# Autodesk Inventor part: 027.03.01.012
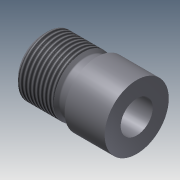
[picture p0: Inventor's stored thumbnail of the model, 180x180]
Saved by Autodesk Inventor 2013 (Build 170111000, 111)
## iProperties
Created: 2005-03
Part Number: 027.03.01.012
Material: Steel, Mild
Document SubType Name: Modeling
Designer: HKostja
Manufacturer: Standard
Standards Organization: Custom
Density: 7.86 g/cm^3
Mass: 77.2847 g
Surface Area: 44.3181 cm^2
Volume: 9.83265 cm^3
Author: HKostja
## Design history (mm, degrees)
revolve "Вращение1" stored, may be unused: angle "d16" = 90 deg
feature "Резьба1" dims "d17" = 10, "d18" = 0
body "Solid1"
sketch "Эскиз1"
  geometry: L1 (0, 0)-(-35, 0); L2 (-35, 9)-(-35, 9.4); L3 (-33.4, 11)-(-20.1, 11); L4 (-20.1, 11)-(-19.146, 10.046); L5 (-18.793, 9.9)-(-16, 9.9); L6 (-15, 10.9)-(-15, 12); L7 (-15, 12)-(0, 12); L8 (0, 12)-(0, 6); L9 (0, 6)-(-32, 6); L10 (-32, 6)-(-35, 9); L11 (-35, 9.4)-(-33.4, 11); A1 r 0.5 centre (-18.793, 10.4) between (-19.146, 10.046) and (-18.793, 9.9); A2 r 1 centre (-16, 10.9) between (-16, 9.9) and (-15, 10.9); 2 further points
  constraints: 22 end point, 6 parallel, 4 point on circle, 4 point on line, 4 tangent, 2 centre point, 1 horizontal, 1 perpendicular, 1 other
  dimensions: "d0" = 35 distance of L1.start L1.end; "d1" = 0 distance from line of L1.end L2; "d2" = 0 distance from line of L1.start L8; "d3" = 20 distance between parallel lines of L6 L2; "d4" = 4 distance from line of point (-19, 9.9) L6; "d5" = 45 deg angle of L5 L4; "d6" = 45 deg angle of L9 L10; "d7" = 24 diameter of L7 L1; "d8" = 22 diameter of L3 L1; "d9" = 19.8 diameter of L5 L1; "d10" = 12 diameter of L9 L1; "d11" = 18 diameter of L2.start L1; "d12" = 0.5 radius of A1; "d13" = 1 radius of A2; "d14" = 1.6 distance of L2.end point (-35, 11); "d15" = 1.6 distance of L3.start point (-35, 11) (= d14)
